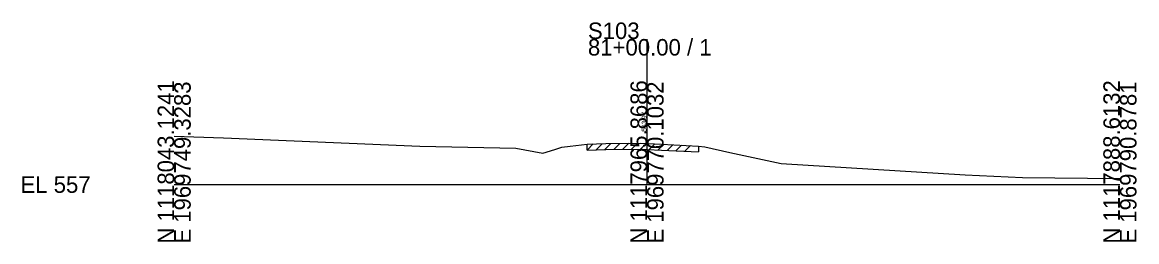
# Model space of a CAD drawing. Extents: x -26 to 163, y -10 to 45020.
# Drawn here: x -25.7 to 162.8, y 39990.3 to 40027.5 of the extents above; entities that cross this region are included whole.
import ezdxf

# ---------------------------------------------------------------- set-up
doc = ezdxf.new("R2010")
doc.units = 0
for name, color, linetype in [('RD_GPK_XS_Cell', 7, 'Continuous'), ('RD_XS_ExGround', 7, 'Continuous'), ('RD_XS_ExPaveRet', 7, 'Continuous'), ('RD_XS_TX_Elev_EX', 7, 'Continuous')]:
    doc.layers.add(name, color=color, linetype=linetype)

msp = doc.modelspace()

# ---------------------------------------------------------------- linework, layer by layer
at = {"layer": 'RD_GPK_XS_Cell'}
for p, q in [((80, 40000), (80, 40024.68)), ((0, 40000), (80, 40000)), ((80, 40000), (160, 40000))]:
    msp.add_line(p, q, dxfattribs=at)
at = {"layer": 'RD_XS_ExGround'}
for p, q in [((0, 40008.23), (8.35, 40007.94)), ((8.35, 40007.94), (41.55, 40006.51)), ((66.99, 40006.51), (69.88, 40006.86)), ((69.88, 40006.86), (73.03, 40006.94)), ((73.03, 40006.94), (78.92, 40007.03)), ((78.92, 40007.03), (80, 40006.97)), ((80, 40006.97), (82.44, 40006.84)), ((82.44, 40006.84), (88.7, 40006.53)), ((41.55, 40006.51), (57.79, 40006.16)), ((57.79, 40006.16), (59.3, 40005.87)), ((59.3, 40005.87), (62.36, 40005.34)), ((62.36, 40005.34), (64.42, 40005.97)), ((64.42, 40005.97), (65.6, 40006.34)), ((65.6, 40006.34), (66.99, 40006.51)), ((88.7, 40006.53), (89.8, 40006.4)), ((89.8, 40006.4), (93.99, 40005.42)), ((93.99, 40005.42), (102.71, 40003.55)), ((102.71, 40003.55), (133.82, 40001.66)), ((133.82, 40001.66), (143.54, 40001.18)), ((143.54, 40001.18), (160, 40001.06))]:
    msp.add_line(p, q, dxfattribs=at)
at = {"layer": 'RD_XS_ExPaveRet'}
for p, q in [((69.88, 40005.86), (70.91, 40006.89)), ((69.88, 40005.86), (69.88, 40006.86)), ((71.38, 40005.9), (72.41, 40006.93)), ((72.88, 40005.94), (73.9, 40006.96)), ((74.38, 40005.96), (75.4, 40006.98)), ((75.88, 40005.98), (76.9, 40007)), ((77.38, 40006.01), (78.4, 40007.02)), ((78.88, 40006.03), (79.84, 40006.98)), ((80.38, 40005.95), (81.33, 40006.9)), ((81.88, 40005.87), (82.83, 40006.82)), ((83.38, 40005.79), (84.34, 40006.74)), ((84.88, 40005.72), (85.84, 40006.67)), ((69.88, 40005.86), (73.03, 40005.94)), ((73.03, 40005.94), (78.92, 40006.03)), ((78.92, 40006.03), (80, 40005.97)), ((80, 40005.97), (82.44, 40005.84)), ((82.44, 40005.84), (88.7, 40005.53)), ((86.38, 40005.64), (87.34, 40006.6)), ((88.7, 40006.53), (88.7, 40005.53))]:
    msp.add_line(p, q, dxfattribs=at)

# ---------------------------------------------------------------- texts
at = {"layer": 'RD_GPK_XS_Cell'}
for s, p in [('S103', (70, 40024.68)), ('81+00.00 / 1', (70, 40021.88)), ('EL 557', (-26, 39998.6))]:
    msp.add_text(s, height=2.8, dxfattribs=at).set_placement(p)
for s, p in [('N 1118043.1241', (0, 39990)), ('E 1969749.3283', (2.8, 39990)), ('N 1117965.8686', (80, 39990)), ('E 1969770.1032', (82.8, 39990)), ('N 1117888.6132', (160, 39990)), ('E 1969790.8781', (162.8, 39990))]:
    msp.add_text(s, height=2.8, rotation=90, dxfattribs=at).set_placement(p)
at = {"layer": 'RD_XS_TX_Elev_EX'}
msp.add_text('563.97', height=0.8, rotation=90, dxfattribs=at).set_placement((79.9, 40008.97))

doc.saveas('drawing.dxf')
